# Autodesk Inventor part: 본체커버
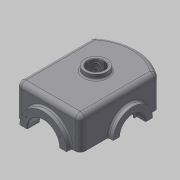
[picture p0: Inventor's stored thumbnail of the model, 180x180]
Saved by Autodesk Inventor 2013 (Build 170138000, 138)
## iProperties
Created: 2019-03
Part Number: 본체커버
Material: 일반
Document SubType Name: Modeling
Designer: mduedu
Density: 2.71 g/cm^3
Mass: 1472.64 g
Surface Area: 1101.88 cm^2
Volume: 543.411 cm^3
Author: mduedu
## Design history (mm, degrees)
sketch "스케치1"
  geometry: L1 (90, -65)-(-65.993, -65); L2 (-65.993, 65)-(90, 65); L3 (90, 65)-(90, -65); L4 (-90, 0)-(90, 0); A1 r 100 centre (10, 0) between (-65.993, 65) and (-65.993, -65); 2 further points
  constraints: 8 end point, 3 point on circle, 2 horizontal alignment, 2 midpoint, 1 centre point, 1 coincident, 1 horizontal, 1 parallel, 1 perpendicular
  dimensions: "d0" = 100 radius of A1; "d2" = 180 distance from line of L3 L4.start; "d3" = 130 distance between parallel lines of L2 L1
extrude "돌출1" new body sketch "스케치1" distance "d4" = 65; taper "d5" = 0 deg
fillet "모깎기1" dims "d6" = 10
fillet "모깎기2" dims "d7" = 10
feature "쉘1" dims "d8" = 10, "d79" = 15
fillet "모깎기3" dims "d9" = 3
fillet "모깎기4" dims "d10" = 3
sketch "스케치2"
  geometry: L1 (110, 0)-(0, 0) reference; A1 r 47.5 centre (55, 0) between (102.5, 0) and (7.5, 0); 1 further point
  constraints: 2 point on circle, 2 point on line, 1 centre point, 1 coincident
  dimensions: "d11" = 95 diameter of A1
extrude "돌출2" join sketch "스케치2" distance "d12" = 10; taper "d13" = 0 deg
hole "구멍1" diameter "d16" = 65; stored, may be unused: countersink angle "d20" = 90 deg, drill point angle "d22" = 118 deg; dims "d14" = 10, "d15" = 10, "d17" = 6, "d18" = 4, "d19" = 2, "d21" = 8
node "작업 평면1"
sketch "스케치3"
  geometry: L1 (61.239, 0)-(-80, 0) reference; L2 (-100, 47.5)-(-100, 0) reference; A1 r 40 centre (7, 0) between (47, 0) and (-33, 0); 1 further point
  constraints: 2 point on circle, 2 point on line, 1 centre point, 1 horizontal alignment
  dimensions: "d24" = 80 diameter of A1; "d25" = 107 distance from line of A1.centre L2
extrude "돌출3" join sketch "스케치3" stored distance "d26" = 10; taper "d27" = 0 deg
hole "구멍2" diameter "d30" = 42; stored, may be unused: countersink angle "d34" = 90 deg, drill point angle "d36" = 118 deg; dims "d28" = 10, "d29" = 10, "d31" = 6, "d32" = 52, "d33" = 18, "d35" = 8
sketch "스케치4" dims "d37" = 65
  geometry: A1 r 40 centre (7, 0) between (47, 0) and (-33, 0) reference; 3 further points
  constraints: 2 vertical alignment, 1 coincident, 2 other
hole "구멍3" sketch "스케치4" at (7, 32.5) diameter "d38" = 3.242; stored, may be unused: countersink angle "d42" = 90 deg, drill point angle "d44" = 118 deg; dims "d39" = 11, "d40" = 52, "d41" = 18, "d43" = 13
sketch "스케치5" dims "d45" = 80
  geometry: A1 r 47.5 centre (55, 0) between (102.5, 0) and (7.5, 0) reference; 5 further points
  constraints: 2 vertical alignment, 1 coincident, 6 other
  dimensions: "d48" = 360 deg dimension on point (55, 0) point (55, -40) (derived)
hole "구멍4" sketch "스케치5" at (55, -40), (89.641, 20), (20.359, 20) diameter "d50" = 3.242; stored, may be unused: countersink angle "d54" = 90 deg, drill point angle "d56" = 118 deg; dims "d51" = 11, "d52" = 52, "d53" = 18, "d55" = 13
fillet "모깎기5" dims "d57" = 3
fillet "모깎기6" dims "d58" = 1
chamfer "모따기1" distance "d59" = 1; stored, may be unused: second distance "d60" = 2, angle "d61" = 45 deg
node "작업 평면2"
sketch "스케치6"
  geometry: L1 (-47, 75)-(33, 75) reference; L2 (-47, -75)-(33, -75) reference; L3 (-7, 75)-(-7, -75); C1 r 22.5 at (-7, 0); 1 further point
  constraints: 3 midpoint, 2 end point, 1 centre point
  dimensions: "d63" = 45 diameter of C1
extrude "돌출4" join sketch "스케치6" stored distance "d64" = 10; taper "d65" = 0 deg
hole "구멍5" diameter "d68" = 33.376; stored, may be unused: countersink angle "d72" = 90 deg, drill point angle "d74" = 118 deg; dims "d66" = 10, "d67" = 10, "d69" = 11, "d70" = 52, "d71" = 18, "d73" = 13
fillet "모깎기7" dims "d75" = 3
chamfer "모따기2" distance "d76" = 1; stored, may be unused: second distance "d77" = 2, angle "d78" = 45 deg
node "솔리드1"
mirror "대칭1"
other parameters: "d23" = 75, "d62" = 75
